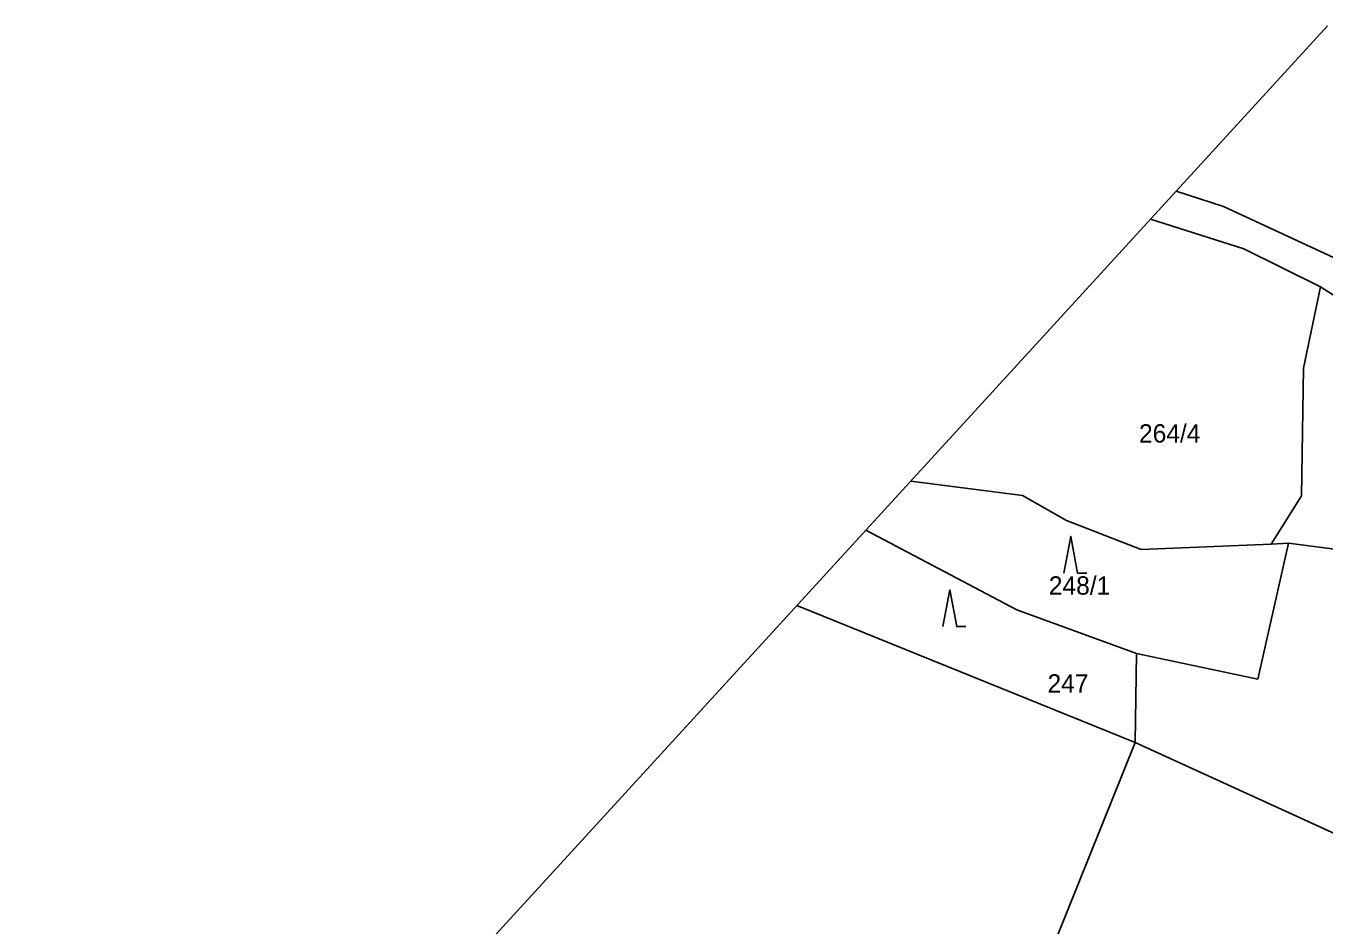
# Model space of a CAD drawing. Extents: x -678683 to -677755, y -1006946 to -1005971.
# Drawn here: x -678541.2 to -678399.9, y -1006533.9 to -1006435.9 of the extents above; entities that cross this region are included whole.
import ezdxf

# ---------------------------------------------------------------- set-up
doc = ezdxf.new("R2010")
doc.units = 0
for name, color, linetype in [('MapaKN - Mladejov+Strelec_dosavani+nova_situace - Vrstva 1', 7, 'Continuous'), ('MapaKN - Mladejov+Strelec_dosavani+nova_situace - Vrstva 18', 7, 'Continuous'), ('MapaKN - Mladejov+Strelec_dosavani+nova_situace - Vrstva 25', 7, 'Continuous'), ('ramy - Sekce lichá', 7, 'Continuous')]:
    doc.layers.add(name, color=color, linetype=linetype)

msp = doc.modelspace()

# ---------------------------------------------------------------- linework, layer by layer
at = {"layer": 'MapaKN - Mladejov+Strelec_dosavani+nova_situace - Vrstva 1'}
for points in [[(-678410.82, -1006455.57), (-678415.98, -1006453.91)], [(-678394.3, -1006463.24), (-678410.82, -1006455.57)], [(-678408.62, -1006460.19), (-678418.75, -1006456.94)], [(-678400.24, -1006464.34), (-678408.62, -1006460.19)], [(-678402.11, -1006473.21), (-678400.24, -1006464.34)], [(-678369.7, -1006483.86), (-678400.24, -1006464.34)], [(-678402.31, -1006487.1), (-678402.11, -1006473.21)], [(-678444.88, -1006485.51), (-678432.69, -1006487.06)], [(-678432.69, -1006487.06), (-678427.91, -1006489.81)], [(-678405.63, -1006492.36), (-678402.31, -1006487.1)], [(-678427.91, -1006489.81), (-678419.78, -1006492.94)], [(-678433.32, -1006499.54), (-678449.78, -1006490.86)], [(-678419.78, -1006492.94), (-678405.63, -1006492.36)], [(-678403.74, -1006492.28), (-678407.09, -1006507.08)], [(-678405.63, -1006492.36), (-678403.74, -1006492.28)], [(-678403.74, -1006492.28), (-678397.88, -1006493.04)], [(-678457.27, -1006499.05), (-678420.43, -1006513.99)], [(-678420.31, -1006504.28), (-678433.32, -1006499.54)], [(-678420.43, -1006513.99), (-678420.31, -1006504.28)], [(-678407.09, -1006507.08), (-678420.31, -1006504.28)], [(-678420.43, -1006513.99), (-678429.12, -1006535.58)], [(-678420.43, -1006513.99), (-678379.35, -1006532.79)]]:
    msp.add_lwpolyline(points, dxfattribs=at)
at = {"layer": 'MapaKN - Mladejov+Strelec_dosavani+nova_situace - Vrstva 25'}
for points in [[(-678428.21, -1006495.53), (-678427.46, -1006491.53), (-678426.71, -1006495.53), (-678425.71, -1006495.53)], [(-678441.37, -1006501.36), (-678440.62, -1006497.36), (-678439.87, -1006501.36), (-678438.87, -1006501.36)]]:
    msp.add_lwpolyline(points, dxfattribs=at)
at = {"layer": 'ramy - Sekce lichá'}
msp.add_line((-678541.24, -1006590.84), (-678399.5, -1006435.89), dxfattribs=at)

# ---------------------------------------------------------------- texts
at = {"layer": 'MapaKN - Mladejov+Strelec_dosavani+nova_situace - Vrstva 18'}
for s, p in [('264/4', (-678420.02, -1006481.3)), ('248/1', (-678429.84, -1006497.88)), ('247', (-678429.98, -1006508.55))]:
    msp.add_text(s, height=2, dxfattribs=at).set_placement(p)

doc.saveas('drawing.dxf')
